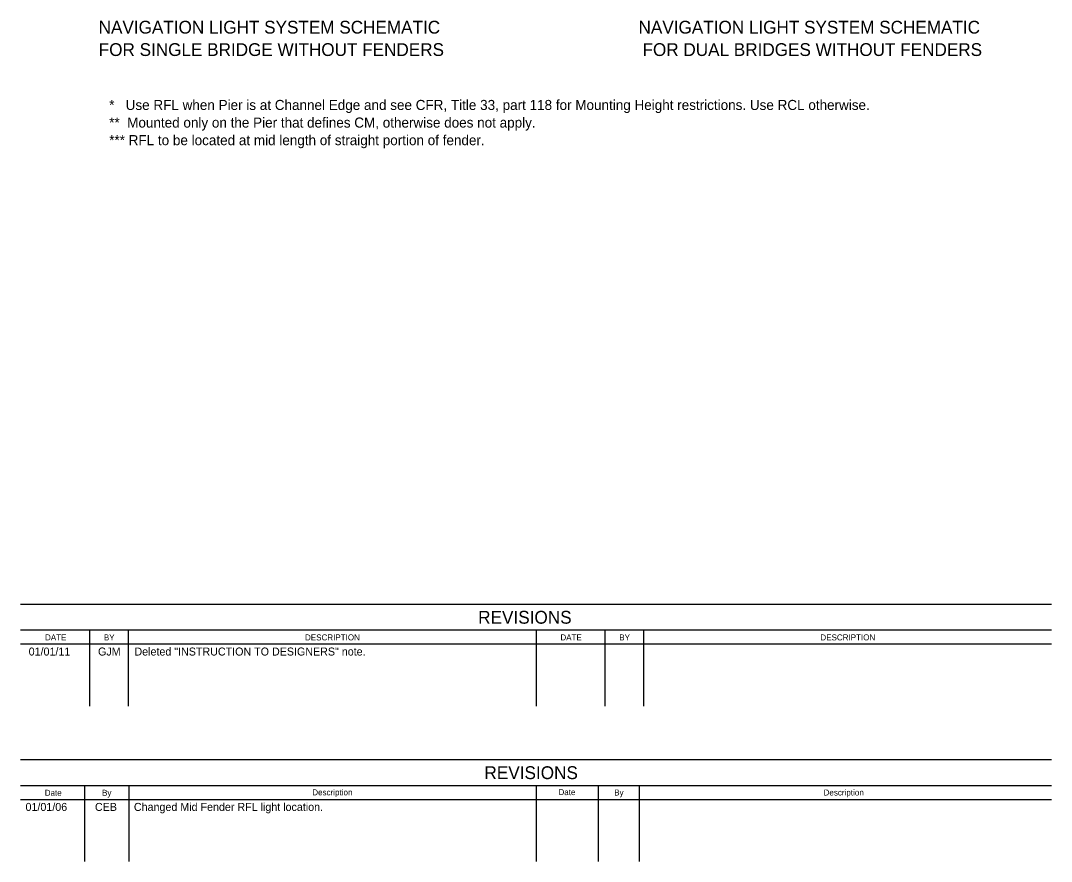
# Model space of a CAD drawing. Extents: x 84082 to 86787, y 72619 to 74101.
# Drawn here: x 84082 to 84855, y 72619 to 73250 of the extents above; entities that cross this region are included whole.
import ezdxf

# ---------------------------------------------------------------- set-up
doc = ezdxf.new("R2010")
doc.units = 0
for name, color, linetype in [('Border', 7, 'Continuous'), ('Dimension', 7, 'Continuous'), ('TextStructures', 7, 'Continuous')]:
    doc.layers.add(name, color=color, linetype=linetype)

msp = doc.modelspace()

# ---------------------------------------------------------------- linework, layer by layer
at = {"layer": 'Border'}
for p, q in [((84855.09, 72811.51), (84082.15, 72811.51)), ((84855.09, 72792.19), (84082.15, 72792.19)), ((84133.77, 72792.19), (84133.77, 72735.38)), ((84162.78, 72792.19), (84162.78, 72735.38)), ((84468.63, 72792.19), (84468.63, 72735.38)), ((84520.25, 72792.19), (84520.25, 72735.38)), ((84549.26, 72792.19), (84549.26, 72735.38)), ((84082.15, 72781.95), (84855.09, 72781.95)), ((84855.09, 72694.94), (84082.13, 72694.94)), ((84855.09, 72675.62), (84082.13, 72675.62)), ((84129.94, 72675.62), (84129.94, 72618.83)), ((84163.39, 72675.62), (84163.39, 72618.83)), ((84468.61, 72675.62), (84468.61, 72618.83)), ((84515.29, 72675.62), (84515.29, 72618.83)), ((84545.9, 72675.62), (84545.9, 72618.83)), ((84082.13, 72665.38), (84855.09, 72665.38))]:
    msp.add_line(p, q, dxfattribs=at)

# ---------------------------------------------------------------- texts
for s, height, p in [('REVISIONS', 9.626, (84429.93, 72680.56)), ('By', 4.504, (84143.21, 72668.06)), ('By', 4.504, (84527.28, 72668.25)), ('01/01/06', 6, (84085.81, 72656.68)), ('CEB', 6, (84137.87, 72656.68)), ('Changed Mid Fender RFL light location.', 6.0004, (84167.08, 72656.68))]:
    msp.add_text(s, height=height, dxfattribs=at).set_placement(p)
for s, height, rotation, p in [('Date', 4.484, 359.86925, (84100.24, 72668.06)), ('Description', 4.5026, 0.04975, (84300.84, 72668.37)), ('Date', 4.484, 359.86925, (84485.49, 72668.56)), ('Description', 4.5026, 0.04975, (84684.27, 72668.25))]:
    msp.add_text(s, height=height, rotation=rotation, dxfattribs=at).set_placement(p)
at = {"layer": 'Dimension'}
for s, height, p in [('NAVIGATION LIGHT SYSTEM SCHEMATIC', 9.6, (84140.65, 73239.79)), ('NAVIGATION LIGHT SYSTEM SCHEMATIC', 9.6, (84545.51, 73239.79)), ('FOR SINGLE BRIDGE WITHOUT FENDERS', 9.6, (84140.7, 73222.99)), ('FOR DUAL BRIDGES WITHOUT FENDERS', 9.6, (84548.48, 73222.99)), ('*   Use RFL when Pier is at Channel Edge and see CFR, Title 33, part 118 for Mounting Height restrictions. Use RCL otherwise.', 7.56002, (84148.57, 73182.48)), ('**  Mounted only on the Pier that defines CM, otherwise does not apply.', 7.56, (84148.57, 73169.28)), ('*** RFL to be located at mid length of straight portion of fender.', 7.56, (84148.57, 73156.08))]:
    msp.add_text(s, height=height, dxfattribs=at).set_placement(p)
at = {"layer": 'TextStructures'}
for s, height, p in [('REVISIONS', 9.626, (84425.23, 72797.13)), ('BY', 4.504, (84144.56, 72784.6)), ('BY', 4.504, (84531.04, 72784.6)), ('01/01/11', 6, (84088.16, 72773.24)), ('GJM', 6, (84140.18, 72773.24)), ('Deleted "INSTRUCTION TO DESIGNERS" note.', 6, (84167.48, 72773.24))]:
    msp.add_text(s, height=height, dxfattribs=at).set_placement(p)
for s, height, rotation, p in [('DATE', 4.484, 359.86925, (84100.47, 72784.63)), ('DESCRIPTION', 4.5026, 0.04975, (84295.39, 72784.58)), ('DATE', 4.484, 359.86925, (84486.95, 72784.63)), ('DESCRIPTION', 4.5026, 0.04975, (84681.87, 72784.58))]:
    msp.add_text(s, height=height, rotation=rotation, dxfattribs=at).set_placement(p)

doc.saveas('drawing.dxf')
